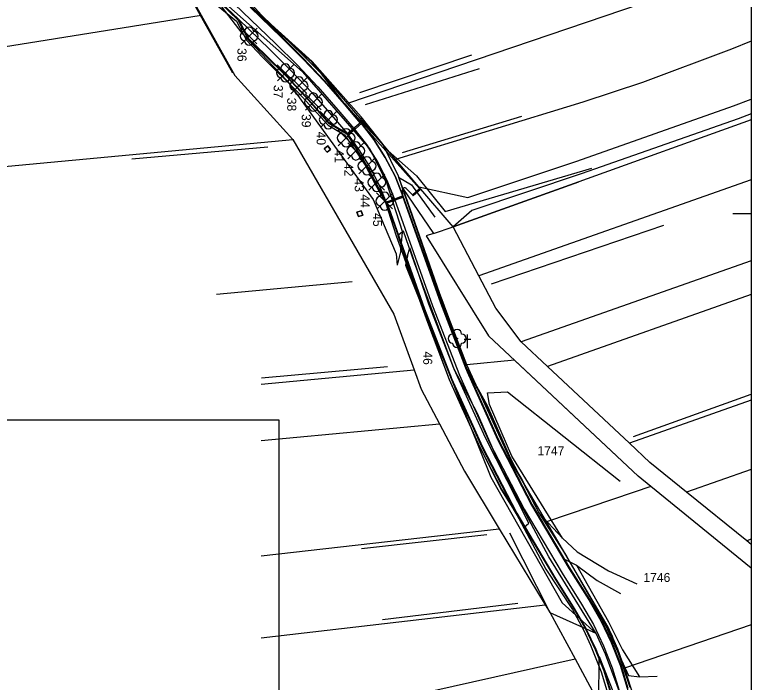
# Model space of a CAD drawing. Extents: x -601800 to -601487, y -1201912 to -1200862.
# Drawn here: x -601649.2 to -601486.7, y -1201385.7 to -1201238.4 of the extents above; entities that cross this region are included whole.
import ezdxf

# ---------------------------------------------------------------- set-up
doc = ezdxf.new("R2010")
doc.units = 0
for name, color, linetype in [('Hranice parcel', 7, 'Continuous'), ('Parcelní čísla', 7, 'Continuous'), ('popis', 7, 'Continuous'), ('u_hrany', 7, 'Continuous'), ('U_keř', 7, 'Continuous'), ('u_návrh', 7, 'Continuous'), ('u_osa', 7, 'Continuous'), ('u_strom', 7, 'Continuous'), ('u_terénní úpravy', 7, 'Continuous'), ('x_rám', 7, 'Continuous')]:
    doc.layers.add(name, color=color, linetype=linetype)

msp = doc.modelspace()

# ---------------------------------------------------------------- linework, layer by layer
at = {"layer": 'Hranice parcel'}
for p, q in [((-601567.94, -1201267.13), (-601575.76, -1201257.99)), ((-601749.75, -1201281.18), (-601587.88, -1201265.89)), ((-601565.18, -1201270.36), (-601567.94, -1201267.13)), ((-601560.05, -1201276.34), (-601565.18, -1201270.36)), ((-601486.66, -1201274.85), (-601546.8, -1201296.02)), ((-601552.5, -1201285.17), (-601560.05, -1201276.34)), ((-601546.8, -1201296.02), (-601552.5, -1201285.17)), ((-601486.66, -1201300.15), (-601531.62, -1201316.01)), ((-601531.62, -1201316.01), (-601537.44, -1201310.56)), ((-601513.53, -1201332.97), (-601531.62, -1201316.01)), ((-601594.83, -1201319.91), (-601561.09, -1201316.74)), ((-601486.66, -1201323.46), (-601513.53, -1201332.97)), ((-601594.83, -1201332.36), (-601555.49, -1201328.67)), ((-601486.66, -1201338.72), (-601500.94, -1201343.73)), ((-601487.64, -1201354.49), (-601500.94, -1201343.73)), ((-601594.83, -1201357.81), (-601542.3, -1201351.82)), ((-601542.3, -1201351.82), (-601532.14, -1201368.61)), ((-601486.66, -1201354.15), (-601487.64, -1201354.49)), ((-601594.83, -1201375.88), (-601532.14, -1201368.61)), ((-601594.83, -1201396.03), (-601525.57, -1201380.51)), ((-601525.57, -1201380.51), (-601520.35, -1201390.13))]:
    msp.add_line(p, q, dxfattribs=at)
for points in [[(-601628.22, -1201204.11), (-601626.16, -1201210.2), (-601621.94, -1201213.75), (-601608.09, -1201238.51)], [(-601486.66, -1201227.7), (-601575.76, -1201257.99)], [(-601575.76, -1201257.99), (-601583.56, -1201248.88), (-601595.54, -1201238.27)], [(-601774, -1201253.38), (-601687.66, -1201251.2), (-601608.09, -1201238.51)], [(-601608.09, -1201238.51), (-601600.65, -1201251.81), (-601587.88, -1201265.89)], [(-601486.66, -1201244.24), (-601491.06, -1201246.01), (-601510.67, -1201253.32), (-601523.83, -1201257.65), (-601565.18, -1201270.36)], [(-601560.05, -1201276.34), (-601549.23, -1201278.7), (-601525.2, -1201270.68), (-601490.61, -1201258.52), (-601486.66, -1201257.02)], [(-601486.66, -1201260.23), (-601489.59, -1201261.34), (-601524.21, -1201273.51), (-601548.32, -1201281.56), (-601552.5, -1201285.17)], [(-601486.66, -1201261.59), (-601524.69, -1201275.26), (-601552.5, -1201285.17)], [(-601587.88, -1201265.89), (-601565.6, -1201304.49), (-601561.09, -1201316.74)], [(-601549.44, -1201315.65), (-601555, -1201301.25), (-601559.75, -1201287.64), (-601564.51, -1201274), (-601567.94, -1201267.13)], [(-601486.66, -1201292.69), (-601537.44, -1201310.56)], [(-601537.44, -1201310.56), (-601543.06, -1201303.13), (-601546.8, -1201296.02)], [(-601508.86, -1201342.47), (-601511.66, -1201340.2), (-601538.92, -1201314.66), (-601549.44, -1201315.65)], [(-601531.84, -1201350.34), (-601539.52, -1201337.25), (-601549.44, -1201315.65)], [(-601561.09, -1201316.74), (-601559.5, -1201321.05), (-601555.49, -1201328.67)], [(-601555.49, -1201328.67), (-601550, -1201339.12), (-601542.3, -1201351.82)], [(-601500.94, -1201343.73), (-601509.03, -1201337.18), (-601513.53, -1201332.97)], [(-601508.86, -1201342.47), (-601512.53, -1201343.73), (-601531.84, -1201350.34)], [(-601486.66, -1201360.54), (-601508.86, -1201342.47)], [(-601514.66, -1201382.62), (-601516.09, -1201378.41), (-601518.22, -1201373.55), (-601531.84, -1201350.34)], [(-601486.66, -1201355.28), (-601487.64, -1201354.49)], [(-601532.14, -1201368.61), (-601531.08, -1201370.35), (-601525.57, -1201380.51)], [(-601486.66, -1201373.03), (-601514.66, -1201382.62)], [(-601511.82, -1201455.51), (-601511.63, -1201442.04), (-601509.82, -1201414.6), (-601509.57, -1201401.34), (-601512.41, -1201389.28), (-601514.66, -1201382.62)]]:
    msp.add_lwpolyline(points, dxfattribs=at)
at = {"layer": 'u_hrany'}
for p, q in [((-601550.03, -1201309.99), (-601548.53, -1201309.99)), ((-601549.28, -1201311.99), (-601549.28, -1201308.99))]:
    msp.add_line(p, q, dxfattribs=at)
for points in [[(-601566.78, -1201268.44), (-601572.76, -1201260.92), (-601583.6, -1201248.74), (-601597.1, -1201236.47), (-601610.74, -1201223.52), (-601619.92, -1201207.39), (-601623.94, -1201192.61)], [(-601624.54, -1201202.66), (-601622.88, -1201208.1), (-601618.52, -1201216.62), (-601613.18, -1201225.1), (-601607.2, -1201231.89), (-601597.53, -1201240.51), (-601585.7, -1201250.99), (-601570.84, -1201268.04), (-601567.28, -1201275.16), (-601563.64, -1201286.39)], [(-601628.64, -1201204.61), (-601626.16, -1201210.2), (-601621.94, -1201213.75), (-601615.14, -1201226.21), (-601601.18, -1201251.22)], [(-601607.2, -1201231.89), (-601599.12, -1201242.46), (-601589.13, -1201252.96), (-601570.11, -1201279.18), (-601565.04, -1201291.14), (-601564.82, -1201293.65)], [(-601573.06, -1201255.54), (-601548.33, -1201247.21)], [(-601571.8, -1201258.19), (-601546.62, -1201250.23)], [(-601563.62, -1201268.83), (-601537.32, -1201260.75)], [(-601593.36, -1201267.61), (-601623.37, -1201270.29)], [(-601566.78, -1201268.44), (-601560.54, -1201273.93)], [(-601554.25, -1201281.85), (-601521.82, -1201272.23)], [(-601564.55, -1201274.22), (-601561.66, -1201275.95)], [(-601564.55, -1201274.22), (-601554.98, -1201301.75), (-601550.1, -1201315.28), (-601544.95, -1201324.64), (-601539.81, -1201336.34), (-601533.54, -1201348.31)], [(-601560.54, -1201273.93), (-601554.25, -1201281.85)], [(-601556.83, -1201286.65), (-601552.5, -1201285.17), (-601524.69, -1201275.26)], [(-601563.6, -1201276.76), (-601556.83, -1201286.65), (-601558.4, -1201287.18), (-601544.66, -1201309.28)], [(-601561.66, -1201275.95), (-601556.52, -1201283.06)], [(-601543.97, -1201297.79), (-601505.98, -1201284.83)], [(-601564, -1201290.43), (-601563.64, -1201286.39)], [(-601564, -1201290.43), (-601564.82, -1201293.65)], [(-601562.57, -1201291.58), (-601562.06, -1201289.84)], [(-601541.87, -1201338.39), (-601547.11, -1201326.43), (-601552.28, -1201316.63), (-601557.82, -1201302.28), (-601562.06, -1201289.84)], [(-601562.57, -1201291.58), (-601563.01, -1201293.69)], [(-601563.01, -1201293.69), (-601544.18, -1201340.47), (-601528.42, -1201368.16), (-601520.9, -1201374.92)], [(-601574.78, -1201297.37), (-601604.69, -1201300.14)], [(-601544.66, -1201309.28), (-601511.66, -1201340.2)], [(-601566.95, -1201316.09), (-601594.74, -1201318.58)], [(-601544.47, -1201324.44), (-601544.87, -1201321.81), (-601540.45, -1201321.63), (-601515.6, -1201341.33)], [(-601512.68, -1201331.45), (-601486.66, -1201322.14)], [(-601528.36, -1201353.88), (-601539.51, -1201335.83), (-601544.47, -1201324.44)], [(-601520.9, -1201374.92), (-601531.36, -1201358), (-601541.87, -1201338.39)], [(-601533.54, -1201348.31), (-601528.36, -1201353.88), (-601525.06, -1201356.91)], [(-601545.02, -1201353.14), (-601572.72, -1201356.26)], [(-601520.9, -1201374.92), (-601531.08, -1201370.35), (-601539.97, -1201352.81)], [(-601525.06, -1201356.91), (-601518.17, -1201361.09), (-601511.91, -1201364)], [(-601528.04, -1201358.49), (-601525.27, -1201359.89)], [(-601528.04, -1201358.49), (-601518.86, -1201373.11), (-601513.78, -1201384.24)], [(-601525.27, -1201359.89), (-601520.66, -1201363.23), (-601515.51, -1201366.15)], [(-601525.27, -1201359.89), (-601518.2, -1201372.38), (-601515.12, -1201378.53), (-601511.32, -1201384.48)], [(-601538.16, -1201368.3), (-601568.07, -1201371.92)], [(-601510.66, -1201493.25), (-601511.13, -1201487.34), (-601514.2, -1201454.81), (-601514.64, -1201441.92), (-601513.13, -1201401.75), (-601514.86, -1201390.2), (-601518.87, -1201379.54), (-601520.9, -1201374.92)], [(-601517.26, -1201405.61), (-601520.32, -1201390.19), (-601520.24, -1201380), (-601515.97, -1201390.87)], [(-601513.78, -1201384.24), (-601511.32, -1201384.48)], [(-601511.32, -1201384.48), (-601507.43, -1201384.34)]]:
    msp.add_lwpolyline(points, dxfattribs=at)
at = {"layer": 'U_keř'}
for p, q in [((-601599.31, -1201241.3), (-601595.77, -1201244.84)), ((-601595.74, -1201241.34), (-601599.27, -1201244.87)), ((-601591.29, -1201249.42), (-601587.75, -1201252.95)), ((-601587.72, -1201249.45), (-601591.25, -1201252.99)), ((-601588.31, -1201252.26), (-601584.78, -1201255.8)), ((-601584.74, -1201252.3), (-601588.28, -1201255.83)), ((-601585.11, -1201255.85), (-601581.58, -1201259.39)), ((-601581.54, -1201255.89), (-601585.08, -1201259.42)), ((-601581.81, -1201259.73), (-601578.28, -1201263.27)), ((-601578.24, -1201259.77), (-601581.78, -1201263.3)), ((-601577.89, -1201263.77), (-601574.36, -1201267.3)), ((-601574.32, -1201263.8), (-601577.86, -1201267.34)), ((-601575.74, -1201266.64), (-601572.21, -1201270.18)), ((-601572.17, -1201266.68), (-601575.71, -1201270.21)), ((-601573.29, -1201269.95), (-601569.76, -1201273.48)), ((-601569.72, -1201269.98), (-601573.26, -1201273.52)), ((-601571.13, -1201273.57), (-601567.6, -1201277.1)), ((-601567.56, -1201273.6), (-601571.1, -1201277.14)), ((-601569.37, -1201277.72), (-601565.83, -1201281.26)), ((-601565.8, -1201277.76), (-601569.33, -1201281.29))]:
    msp.add_line(p, q, dxfattribs=at)
msp.add_lwpolyline([(-601563.44, -1201286.17), (-601564.68, -1201287.09), (-601558.77, -1201304.21), (-601553.37, -1201318.89), (-601548.87, -1201328.82), (-601546.52, -1201333.97), (-601541.7, -1201343.26), (-601536.83, -1201351.45), (-601535.74, -1201350.58), (-601545.34, -1201331.76), (-601552.28, -1201316.63), (-601561.01, -1201293.14), (-601563.44, -1201286.17)], dxfattribs=at)
for centre in [(-601597.5, -1201243.11), (-601589.49, -1201251.22), (-601586.51, -1201254.07), (-601583.31, -1201257.66), (-601580.01, -1201261.54)]:
    msp.add_circle(centre, 0.1, dxfattribs=at)
for centre, start, end in [((-601597.5, -1201242.11), 0, 180), ((-601598.5, -1201243.11), 90, 270), ((-601596.5, -1201243.11), 270, 90), ((-601597.5, -1201244.11), 180, 0), ((-601589.49, -1201250.22), 0, 180), ((-601590.49, -1201251.22), 90, 270), ((-601588.49, -1201251.22), 270, 90), ((-601589.49, -1201252.22), 180, 0), ((-601587.51, -1201254.07), 90, 270), ((-601586.51, -1201253.07), 0, 180), ((-601585.51, -1201254.07), 270, 90), ((-601586.51, -1201255.07), 180, 0), ((-601583.31, -1201256.66), 0, 180), ((-601584.31, -1201257.66), 90, 270), ((-601582.31, -1201257.66), 270, 90), ((-601583.31, -1201258.66), 180, 0), ((-601580.01, -1201260.54), 0, 180), ((-601581.01, -1201261.54), 90, 270), ((-601579.01, -1201261.54), 270, 90), ((-601580.01, -1201262.54), 180, 0)]:
    msp.add_arc(centre, 1, start, end, dxfattribs=at)
at = {"layer": 'u_návrh'}
for p, q in [((-601599.98, -1201239.49), (-601597.78, -1201243.69)), ((-601599.86, -1201239.4), (-601597.66, -1201243.6)), ((-601575.93, -1201264.78), (-601579.93, -1201262.36)), ((-601575.81, -1201264.68), (-601579.83, -1201262.25)), ((-601559.87, -1201276.73), (-601572.85, -1201262.23)), ((-601563.54, -1201278.37), (-601563.66, -1201277.12)), ((-601561.46, -1201278.1), (-601562.81, -1201276.73)), ((-601559.87, -1201276.73), (-601561.46, -1201278.1)), ((-601559.67, -1201276.96), (-601561.27, -1201278.33)), ((-601559.67, -1201276.96), (-601559.87, -1201276.73)), ((-601561.46, -1201278.1), (-601561.27, -1201278.33))]:
    msp.add_line(p, q, dxfattribs=at)
for points in [[(-601572.75, -1201077.5), (-601575.4, -1201082.24), (-601576.9, -1201084.6), (-601579.76, -1201088.85), (-601582.83, -1201092.93), (-601586.12, -1201096.86), (-601605.47, -1201118.82), (-601612.1, -1201127.19), (-601617.84, -1201136.26), (-601622.59, -1201145.87), (-601626.29, -1201155.88), (-601627.44, -1201159.58), (-601628.96, -1201165.79), (-601629.7, -1201172.21), (-601629.64, -1201178.67), (-601628.79, -1201185.01), (-601625.54, -1201201.39), (-601623.73, -1201208.12), (-601620.99, -1201214.62), (-601617.4, -1201220.68), (-601613.06, -1201226.15), (-601607.6, -1201232.16), (-601599.98, -1201239.49)], [(-601572.61, -1201077.56), (-601575.27, -1201082.31), (-601576.77, -1201084.68), (-601579.64, -1201088.94), (-601582.71, -1201093.02), (-601586, -1201096.96), (-601605.35, -1201118.92), (-601611.97, -1201127.28), (-601617.7, -1201136.33), (-601622.45, -1201145.93), (-601626.15, -1201155.93), (-601627.3, -1201159.62), (-601628.81, -1201165.82), (-601629.55, -1201172.22), (-601629.49, -1201178.66), (-601628.64, -1201184.99), (-601625.4, -1201201.35), (-601623.58, -1201208.08), (-601620.85, -1201214.55), (-601617.27, -1201220.6), (-601612.94, -1201226.05), (-601607.49, -1201232.05), (-601599.86, -1201239.4)], [(-601610.02, -1201223.54), (-601604.73, -1201229.37), (-601590.25, -1201243.3), (-601585.48, -1201248.06), (-601580.85, -1201252.98), (-601576.41, -1201258.04), (-601572.85, -1201262.23)], [(-601597.31, -1201236.72), (-601590.36, -1201243.41), (-601585.58, -1201248.16), (-601580.96, -1201253.08), (-601576.52, -1201258.14), (-601572.99, -1201262.29)], [(-601599.86, -1201239.4), (-601592.94, -1201246.05), (-601588.24, -1201250.74), (-601583.7, -1201255.57), (-601579.32, -1201260.56), (-601575.82, -1201264.69)], [(-601597.78, -1201243.69), (-601594.1, -1201247.23), (-601589.42, -1201251.89), (-601584.92, -1201256.68), (-601579.93, -1201262.36)], [(-601597.66, -1201243.6), (-601593.99, -1201247.13), (-601589.31, -1201251.78), (-601584.81, -1201256.58), (-601579.83, -1201262.25)], [(-601572.88, -1201262.19), (-601574.2, -1201263.31), (-601575.93, -1201264.78)], [(-601572.68, -1201262.42), (-601574, -1201263.54), (-601575.77, -1201265.04)], [(-601574.22, -1201263.72), (-601571.63, -1201267.06), (-601569.2, -1201270.88), (-601567.12, -1201274.89), (-601565.41, -1201279.08), (-601563.54, -1201278.37), (-601565.3, -1201274.05), (-601567.47, -1201269.88), (-601570, -1201265.91), (-601572.69, -1201262.43), (-601574, -1201263.54), (-601574.22, -1201263.72)], [(-601572.85, -1201262.23), (-601570, -1201265.91), (-601567.47, -1201269.88), (-601565.3, -1201274.05), (-601563.54, -1201278.37)], [(-601574.22, -1201263.72), (-601575.64, -1201264.93), (-601573.27, -1201268.22), (-601570.93, -1201271.88), (-601568.94, -1201275.73), (-601567.28, -1201279.79), (-601565.56, -1201279.14), (-601565.41, -1201279.08), (-601567.12, -1201274.89), (-601569.2, -1201270.88), (-601571.63, -1201267.06), (-601574.22, -1201263.72)], [(-601575.93, -1201264.78), (-601573.6, -1201268.45), (-601571.28, -1201272.08), (-601569.3, -1201275.9), (-601567.28, -1201279.79)], [(-601575.82, -1201264.69), (-601573.27, -1201268.22), (-601570.93, -1201271.88), (-601568.94, -1201275.73), (-601567.28, -1201279.79)], [(-601579.84, -1201267.73), (-601580.16, -1201267.34), (-601580.94, -1201267.96), (-601580.31, -1201268.74), (-601579.53, -1201268.12), (-601579.84, -1201267.73)], [(-601563.54, -1201278.37), (-601565.56, -1201279.14), (-601567.28, -1201279.79)], [(-601563.44, -1201278.65), (-601565.47, -1201279.42), (-601567.18, -1201280.08)], [(-601563.68, -1201278.42), (-601555.29, -1201301.98), (-601549.75, -1201316.3)], [(-601563.54, -1201278.37), (-601555.15, -1201301.93), (-601549.25, -1201317.17), (-601542.54, -1201332.04), (-601535.03, -1201346.52), (-601526.72, -1201360.59), (-601522.42, -1201367.44), (-601519.75, -1201372.06), (-601517.42, -1201376.89), (-601515.46, -1201381.89), (-601513.89, -1201386.98)], [(-601567.28, -1201279.79), (-601558.9, -1201303.32), (-601552.94, -1201318.72), (-601546.14, -1201333.79), (-601538.53, -1201348.46), (-601530.13, -1201362.67), (-601525.84, -1201369.5), (-601523.29, -1201373.93), (-601521.09, -1201378.49), (-601519.24, -1201383.21), (-601517.73, -1201388.09)], [(-601567.14, -1201279.74), (-601558.76, -1201303.27), (-601553.13, -1201317.83)], [(-601572.61, -1201282.12), (-601572.78, -1201281.64), (-601573.72, -1201281.98), (-601573.38, -1201282.92), (-601572.44, -1201282.59), (-601572.61, -1201282.12)], [(-601549.75, -1201316.3), (-601549.39, -1201317.23), (-601542.68, -1201332.11), (-601535.16, -1201346.59), (-601526.84, -1201360.67), (-601522.55, -1201367.52), (-601519.89, -1201372.13), (-601517.56, -1201376.95), (-601515.6, -1201381.93), (-601514.03, -1201387.02), (-601512.87, -1201391.36), (-601511.61, -1201396.91), (-601510.79, -1201402.59), (-601510.43, -1201408.32), (-601510.53, -1201414.01), (-601512.26, -1201444.39), (-601512.42, -1201450.21), (-601512.24, -1201456), (-601511.71, -1201461.79), (-601506.5, -1201504.96), (-601506.06, -1201509.37), (-601505.82, -1201513.81), (-601505.77, -1201518.24), (-601506.19, -1201556.5)], [(-601553.14, -1201317.8), (-601552.81, -1201318.66), (-601546.01, -1201333.72), (-601538.39, -1201348.39), (-601530, -1201362.6), (-601525.72, -1201369.43), (-601523.16, -1201373.86), (-601520.96, -1201378.43), (-601519.1, -1201383.16), (-601517.59, -1201388.04), (-601516.46, -1201392.25), (-601515.25, -1201397.59), (-601514.48, -1201402.97), (-601514.13, -1201408.4), (-601514.23, -1201413.88), (-601515.96, -1201444.23), (-601516.12, -1201450.21), (-601515.93, -1201456.22), (-601515.39, -1201462.18), (-601510.17, -1201505.36), (-601509.75, -1201509.65), (-601509.52, -1201513.93), (-601509.47, -1201518.24), (-601509.71, -1201540.62)]]:
    msp.add_lwpolyline(points, dxfattribs=at)
for points in [[(-601580.16, -1201267.34), (-601579.53, -1201268.12), (-601580.31, -1201268.74), (-601580.94, -1201267.96)], [(-601572.78, -1201281.64), (-601572.44, -1201282.59), (-601573.38, -1201282.92), (-601573.72, -1201281.98)]]:
    msp.add_lwpolyline(points, close=True, dxfattribs=at)
msp.add_arc((-601563.16, -1201277.08), 0.5, 44.379, 185.5276, dxfattribs=at)
at = {"layer": 'u_osa'}
msp.add_lwpolyline([(-601606.16, -1201230.76), (-601591.65, -1201244.73), (-601586.91, -1201249.45), (-601582.33, -1201254.32), (-601577.92, -1201259.35), (-601574.4, -1201263.49), (-601571.63, -1201267.06), (-601569.2, -1201270.88), (-601567.12, -1201274.89), (-601565.41, -1201279.08), (-601557.03, -1201302.63), (-601551.1, -1201317.94), (-601544.34, -1201332.91), (-601536.78, -1201347.49), (-601528.42, -1201361.63), (-601524.13, -1201368.47), (-601521.52, -1201372.99), (-601519.26, -1201377.69), (-601517.35, -1201382.55), (-601515.81, -1201387.53)], dxfattribs=at)
at = {"layer": 'u_strom'}
msp.add_lwpolyline([(-601790.89, -1201506.46), (-601590.84, -1201506.46), (-601590.84, -1201327.83), (-601790.89, -1201327.83)], close=True, dxfattribs=at)
for centre in [(-601576.09, -1201265.57), (-601573.94, -1201268.45), (-601571.49, -1201271.75), (-601569.33, -1201275.37), (-601567.57, -1201279.53), (-601551.59, -1201309.85)]:
    msp.add_circle(centre, 0.1, dxfattribs=at)
for centre, start, end in [((-601576.09, -1201264.57), 0, 180), ((-601577.09, -1201265.57), 90, 270), ((-601575.09, -1201265.57), 270, 90), ((-601576.09, -1201266.57), 180, 0), ((-601574.94, -1201268.45), 90, 270), ((-601573.94, -1201267.45), 0, 180), ((-601572.94, -1201268.45), 270, 90), ((-601573.94, -1201269.45), 180, 0), ((-601572.49, -1201271.75), 90, 270), ((-601571.49, -1201270.75), 0, 180), ((-601570.49, -1201271.75), 270, 90), ((-601571.49, -1201272.75), 180, 0), ((-601569.33, -1201274.37), 0, 180), ((-601570.33, -1201275.37), 90, 270), ((-601568.33, -1201275.37), 270, 90), ((-601569.33, -1201276.37), 180, 0), ((-601568.57, -1201279.53), 90, 270), ((-601567.57, -1201278.53), 0, 180), ((-601566.57, -1201279.53), 270, 90), ((-601567.57, -1201280.53), 180, 0), ((-601551.59, -1201308.85), 0, 180), ((-601552.59, -1201309.85), 90, 270), ((-601550.59, -1201309.85), 270, 90), ((-601551.59, -1201310.85), 180, 0)]:
    msp.add_arc(centre, 1, start, end, dxfattribs=at)
at = {"layer": 'u_terénní úpravy'}
for points in [[(-601608.73, -1201232.85), (-601600.31, -1201239.84), (-601598.11, -1201244.01), (-601594.54, -1201247.73), (-601586.63, -1201255.63), (-601586.63, -1201255.63), (-601586.63, -1201255.63), (-601580.05, -1201262.74), (-601576.46, -1201264.91), (-601573.24, -1201269.59), (-601571.86, -1201271.58), (-601569.61, -1201275.94), (-601567.41, -1201279.84), (-601565.04, -1201287.21), (-601558.15, -1201306.25), (-601553.37, -1201318.89), (-601550.55, -1201325.15), (-601546.52, -1201333.97), (-601541.76, -1201343.29), (-601538.58, -1201348.49), (-601532.04, -1201360.74), (-601526.09, -1201369.63), (-601523.66, -1201374.12), (-601522.13, -1201377.5), (-601519.79, -1201383.4), (-601518.29, -1201388.25)], [(-601596.82, -1201236.21), (-601594.79, -1201238.45), (-601585.63, -1201247.3), (-601581.79, -1201251.14), (-601576.86, -1201257.52), (-601573.38, -1201261.35), (-601568.53, -1201266.44), (-601559.67, -1201276.96)], [(-601563.55, -1201276.75), (-601560.47, -1201285.58), (-601555.47, -1201299.92), (-601555, -1201301.25), (-601553.7, -1201304.61), (-601549.71, -1201315.99), (-601546.01, -1201323.12), (-601539.52, -1201337.25), (-601537.34, -1201340.96), (-601533.54, -1201348.31), (-601527.44, -1201357.91), (-601522.35, -1201366.76), (-601519.36, -1201371.81), (-601517.43, -1201375.34), (-601516.3, -1201378.72), (-601515.18, -1201381.79), (-601513.5, -1201386.77)]]:
    msp.add_lwpolyline(points, dxfattribs=at)
at = {"layer": 'x_rám'}
msp.add_line((-601486.66, -1201282.35), (-601490.7, -1201282.35), dxfattribs=at)
msp.add_lwpolyline([(-601486.66, -1200862.35), (-601486.66, -1201912.35), (-601783.66, -1201912.35), (-601783.66, -1200862.35)], close=True, dxfattribs=at)

# ---------------------------------------------------------------- texts
at = {"layer": 'Parcelní čísla'}
for s, p in [('1747', (-601533.86, -1201335.61)), ('1746', (-601510.48, -1201363.58))]:
    msp.add_text(s, height=2, dxfattribs=at).set_placement(p)
at = {"layer": 'popis'}
for s, p in [('36', (-601600.09, -1201245.75)), ('37', (-601592.07, -1201253.87)), ('38', (-601589.1, -1201256.71)), ('39', (-601585.89, -1201260.3)), ('40', (-601582.6, -1201264.18)), ('41', (-601578.6, -1201268.14)), ('42', (-601576.52, -1201271.09)), ('43', (-601574.19, -1201274.52)), ('44', (-601572.91, -1201278.02)), ('45', (-601570.15, -1201282.17)), ('46', (-601559.08, -1201312.68))]:
    msp.add_text(s, height=2, rotation=270, dxfattribs=at).set_placement(p)

doc.saveas('drawing.dxf')
